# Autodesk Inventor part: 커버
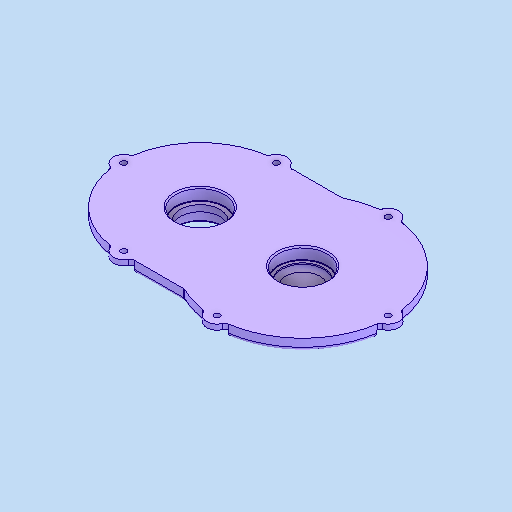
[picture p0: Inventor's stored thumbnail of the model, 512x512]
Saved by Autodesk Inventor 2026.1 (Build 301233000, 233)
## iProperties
Created: 2025-09
Part Number: 커버
Material: 알루미늄 6061
Document SubType Name: Modeling
Designer: PC-30
Density: 2.7 g/cm^3
Appearance: 기본값
Author: jhkim
Sending System: Autodesk Inventor 2026
Preprocessor: ST-DEVELOPER v20.1
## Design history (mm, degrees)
feature "솔리드1"
node "솔리드2"
